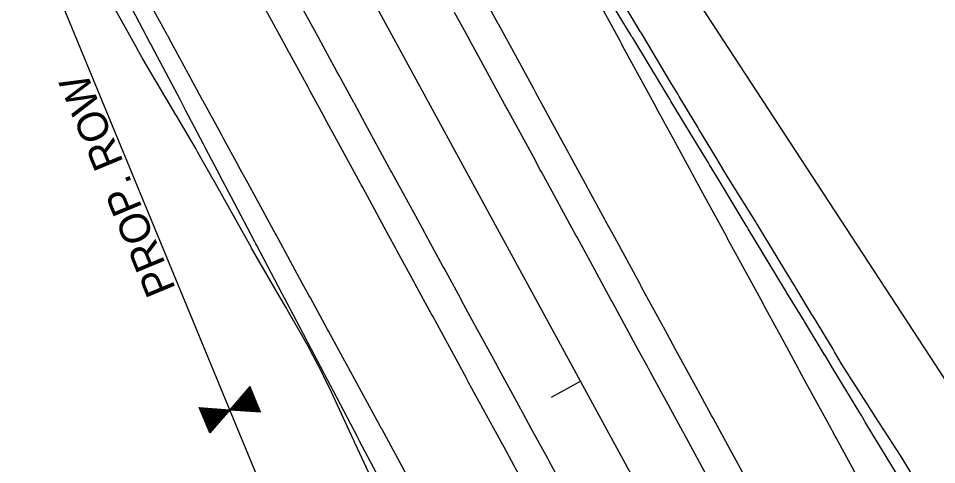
# Model space of a CAD drawing. Extents: x 1627557 to 1636561, y 783843 to 794002.
# Drawn here: x 1627879.8 to 1628047.3, y 785040.7 to 785122 of the extents above; entities that cross this region are included whole.
import ezdxf

# ---------------------------------------------------------------- set-up
doc = ezdxf.new("R2010")
doc.units = 0
for name, color, linetype in [('GATE', 7, 'Continuous'), ('R_Clearzone', 7, 'Continuous'), ('R_Ditch', 7, 'Continuous'), ('R_Horz Alg', 7, 'Continuous'), ('R_Horz Alg Annot', 7, 'Continuous'), ('R_Proposed Const Limits', 7, 'Continuous'), ('R_Proposed Road', 7, 'Continuous'), ('R_Proposed Shoulder', 7, 'Continuous'), ('R_ROW', 7, 'Continuous'), ('R_ROW Annot Labels', 7, 'Continuous')]:
    doc.layers.add(name, color=color, linetype=linetype)

msp = doc.modelspace()

# ---------------------------------------------------------------- linework, layer by layer
at = {"layer": 'GATE'}
for p, q in [((1627921.73, 785054.58), (1627923.49, 785050.35)), ((1627921.81, 785054.67), (1627923.6, 785050.34)), ((1627921.88, 785054.75), (1627923.71, 785050.33)), ((1627921.95, 785054.84), (1627923.82, 785050.32)), ((1627922.03, 785054.92), (1627923.93, 785050.31)), ((1627920.27, 785052.9), (1627921.26, 785050.51)), ((1627920.34, 785052.98), (1627921.37, 785050.5)), ((1627920.42, 785053.06), (1627921.48, 785050.49)), ((1627920.49, 785053.15), (1627921.59, 785050.48)), ((1627920.56, 785053.23), (1627921.7, 785050.47)), ((1627920.63, 785053.32), (1627921.82, 785050.47)), ((1627920.71, 785053.4), (1627921.93, 785050.46)), ((1627920.78, 785053.49), (1627922.04, 785050.45)), ((1627920.85, 785053.57), (1627922.15, 785050.44)), ((1627920.93, 785053.66), (1627922.26, 785050.43)), ((1627921, 785053.74), (1627922.37, 785050.43)), ((1627921.07, 785053.82), (1627922.48, 785050.42)), ((1627921.15, 785053.91), (1627922.6, 785050.41)), ((1627921.22, 785053.99), (1627922.71, 785050.4)), ((1627921.29, 785054.08), (1627922.82, 785050.39)), ((1627921.37, 785054.16), (1627922.93, 785050.39)), ((1627921.44, 785054.25), (1627923.04, 785050.38)), ((1627921.51, 785054.33), (1627923.15, 785050.37)), ((1627921.59, 785054.42), (1627923.26, 785050.36)), ((1627921.66, 785054.5), (1627923.38, 785050.35)), ((1627918.88, 785051.29), (1627919.14, 785050.66)), ((1627918.95, 785051.38), (1627919.25, 785050.65)), ((1627919.02, 785051.46), (1627919.36, 785050.64)), ((1627919.1, 785051.54), (1627919.47, 785050.63)), ((1627919.17, 785051.63), (1627919.58, 785050.63)), ((1627919.24, 785051.71), (1627919.7, 785050.62)), ((1627919.32, 785051.8), (1627919.81, 785050.61)), ((1627919.39, 785051.88), (1627919.92, 785050.6)), ((1627919.46, 785051.97), (1627920.03, 785050.59)), ((1627919.54, 785052.05), (1627920.14, 785050.59)), ((1627919.61, 785052.14), (1627920.25, 785050.58)), ((1627919.68, 785052.22), (1627920.37, 785050.57)), ((1627919.76, 785052.3), (1627920.48, 785050.56)), ((1627919.83, 785052.39), (1627920.59, 785050.55)), ((1627919.9, 785052.47), (1627920.7, 785050.55)), ((1627919.98, 785052.56), (1627920.81, 785050.54)), ((1627920.05, 785052.64), (1627920.92, 785050.53)), ((1627920.12, 785052.73), (1627921.03, 785050.52)), ((1627920.2, 785052.81), (1627921.15, 785050.51)), ((1627912.88, 785051.1), (1627914.76, 785046.55)), ((1627912.99, 785051.1), (1627914.84, 785046.63)), ((1627913.1, 785051.09), (1627914.91, 785046.72)), ((1627913.21, 785051.08), (1627914.98, 785046.8)), ((1627913.32, 785051.07), (1627915.06, 785046.89)), ((1627913.44, 785051.06), (1627915.13, 785046.97)), ((1627913.55, 785051.06), (1627915.2, 785047.06)), ((1627913.66, 785051.05), (1627915.28, 785047.14)), ((1627913.77, 785051.04), (1627915.35, 785047.22)), ((1627913.88, 785051.03), (1627915.42, 785047.31)), ((1627913.99, 785051.02), (1627915.5, 785047.39)), ((1627914.1, 785051.02), (1627915.57, 785047.48)), ((1627914.22, 785051.01), (1627915.64, 785047.56)), ((1627914.33, 785051), (1627915.71, 785047.65)), ((1627914.44, 785050.99), (1627915.79, 785047.73)), ((1627914.55, 785050.98), (1627915.86, 785047.82)), ((1627914.66, 785050.98), (1627915.93, 785047.9)), ((1627914.77, 785050.97), (1627916.01, 785047.98)), ((1627914.88, 785050.96), (1627916.08, 785048.07)), ((1627915, 785050.95), (1627916.15, 785048.15)), ((1627915.11, 785050.94), (1627916.23, 785048.24)), ((1627915.22, 785050.94), (1627916.3, 785048.32)), ((1627915.33, 785050.93), (1627916.37, 785048.41)), ((1627915.44, 785050.92), (1627916.45, 785048.49)), ((1627915.55, 785050.91), (1627916.52, 785048.58)), ((1627915.67, 785050.9), (1627916.59, 785048.66)), ((1627915.78, 785050.9), (1627916.67, 785048.74)), ((1627915.89, 785050.89), (1627916.74, 785048.83)), ((1627916, 785050.88), (1627916.81, 785048.91)), ((1627916.11, 785050.87), (1627916.89, 785049)), ((1627916.22, 785050.86), (1627916.96, 785049.08)), ((1627916.33, 785050.86), (1627917.03, 785049.17)), ((1627916.45, 785050.85), (1627917.11, 785049.25)), ((1627916.56, 785050.84), (1627917.18, 785049.34)), ((1627916.67, 785050.83), (1627917.25, 785049.42)), ((1627916.78, 785050.82), (1627917.33, 785049.5)), ((1627916.89, 785050.82), (1627917.4, 785049.59)), ((1627917, 785050.81), (1627917.47, 785049.67)), ((1627917.12, 785050.8), (1627917.55, 785049.76)), ((1627917.23, 785050.79), (1627917.62, 785049.84)), ((1627917.34, 785050.79), (1627917.69, 785049.93)), ((1627917.45, 785050.78), (1627917.77, 785050.01)), ((1627917.56, 785050.77), (1627917.84, 785050.1)), ((1627917.67, 785050.76), (1627917.91, 785050.18)), ((1627917.78, 785050.75), (1627917.99, 785050.26)), ((1627917.9, 785050.75), (1627918.06, 785050.35)), ((1627918.01, 785050.74), (1627918.13, 785050.43)), ((1627918.12, 785050.73), (1627918.21, 785050.52)), ((1627918.23, 785050.72), (1627918.28, 785050.6)), ((1627918.34, 785050.71), (1627918.35, 785050.69)), ((1627918.44, 785050.78), (1627918.47, 785050.7)), ((1627918.51, 785050.87), (1627918.58, 785050.7)), ((1627918.58, 785050.95), (1627918.69, 785050.69)), ((1627918.66, 785051.04), (1627918.8, 785050.68)), ((1627918.73, 785051.12), (1627918.92, 785050.67)), ((1627918.8, 785051.21), (1627919.03, 785050.66))]:
    msp.add_line(p, q, dxfattribs=at)
for points in [[(1627922.04, 785054.93), (1627918.37, 785050.71), (1627923.95, 785050.31)], [(1627912.8, 785051.11), (1627918.37, 785050.71), (1627914.71, 785046.49)]]:
    msp.add_lwpolyline(points, close=True, dxfattribs=at)
at = {"layer": 'R_Clearzone'}
for points in [[(1627950.73, 785038.65), (1627946.07, 785047.2), (1627945.94, 785047.43), (1627945.85, 785047.61), (1627945.73, 785047.82), (1627941.16, 785056.21), (1627939.56, 785059.13), (1627939.35, 785059.52), (1627936.37, 785064.99), (1627936.18, 785065.33), (1627933.06, 785071.07), (1627932.86, 785071.43), (1627931.58, 785073.77), (1627926.8, 785082.55), (1627926.63, 785082.84), (1627926.51, 785083.08), (1627926.39, 785083.29), (1627922.01, 785091.33), (1627919.96, 785095.09), (1627919.93, 785095.14), (1627917.22, 785100.11), (1627916.84, 785100.81), (1627913.46, 785107), (1627913.41, 785107.1), (1627912.43, 785108.89), (1627907.65, 785117.67), (1627907.04, 785118.78), (1627907, 785118.85), (1627906.86, 785119.11), (1627902.86, 785126.45)], [(1628033.09, 785038), (1628028.96, 785045.57), (1628028.78, 785045.9), (1628028.31, 785046.78), (1628028.04, 785047.26), (1628023.52, 785055.56), (1628022.3, 785057.79), (1628022.05, 785058.25), (1628018.73, 785064.34), (1628018.49, 785064.77), (1628015.79, 785069.73), (1628015.56, 785070.16), (1628013.95, 785073.12), (1628009.28, 785081.66), (1628009.16, 785081.89), (1628009.06, 785082.07), (1628008.95, 785082.29), (1628004.37, 785090.67), (1628002.78, 785093.6), (1628002.57, 785093.98), (1627999.58, 785099.45), (1627999.4, 785099.8), (1627996.27, 785105.53), (1627996.07, 785105.9), (1627994.8, 785108.23), (1627990.01, 785117.01), (1627989.85, 785117.31), (1627989.72, 785117.54), (1627989.61, 785117.75), (1627985.22, 785125.79)]]:
    msp.add_lwpolyline(points, dxfattribs=at)
at = {"layer": 'R_Ditch'}
for points in [[(1628041.37, 785036.75), (1628038.75, 785041.08), (1628034.27, 785048.46), (1628034.07, 785048.79), (1628033.56, 785049.64), (1628033.27, 785050.11), (1628028.37, 785058.2), (1628027.05, 785060.38), (1628026.77, 785060.83), (1628023.18, 785066.76), (1628022.92, 785067.18), (1628019.99, 785072.02), (1628019.73, 785072.44), (1628017.99, 785075.32), (1628012.93, 785083.65), (1628012.8, 785083.88), (1628012.69, 785084.05), (1628012.57, 785084.26), (1628007.61, 785092.44), (1628005.88, 785095.29), (1628005.65, 785095.67), (1628002.42, 785101), (1628002.21, 785101.33), (1627998.82, 785106.92), (1627998.61, 785107.28), (1627997.23, 785109.56), (1627992.04, 785118.12), (1627991.86, 785118.41), (1627991.72, 785118.64), (1627991.6, 785118.84), (1627986.85, 785126.68)], [(1627946.58, 785036.39), (1627942.05, 785045), (1627941.92, 785045.24), (1627941.83, 785045.42), (1627941.72, 785045.63), (1627937.26, 785054.08), (1627935.71, 785057.03), (1627935.51, 785057.42), (1627932.6, 785062.93), (1627932.42, 785063.28), (1627929.38, 785069.06), (1627929.18, 785069.43), (1627927.94, 785071.78), (1627923.28, 785080.63), (1627923.12, 785080.93), (1627923, 785081.16), (1627922.89, 785081.38), (1627918.62, 785089.48), (1627916.62, 785093.27), (1627916.6, 785093.32), (1627913.96, 785098.33), (1627913.59, 785099.04), (1627910.3, 785105.27), (1627910.25, 785105.38), (1627909.3, 785107.18), (1627904.64, 785116.03), (1627904.05, 785117.15), (1627904.01, 785117.22), (1627903.87, 785117.48), (1627899.98, 785124.87)]]:
    msp.add_lwpolyline(points, dxfattribs=at)
at = {"layer": 'R_Horz Alg'}
msp.add_line((1628236.53, 784589.68), (1627810.31, 785371.39), dxfattribs=at)
at = {"layer": 'R_Horz Alg Annot'}
msp.add_lwpolyline([(1627977.07, 785053.01), (1627982.34, 785055.88)], dxfattribs=at)
at = {"layer": 'R_Proposed Const Limits'}
for points in [[(1628043.44, 785037.88), (1628040.79, 785042.19), (1628036.1, 785049.46), (1628035.89, 785049.78), (1628035.36, 785050.62), (1628035.06, 785051.08), (1628029.93, 785059.05), (1628028.67, 785061.26), (1628028.41, 785061.72), (1628024.81, 785067.65), (1628024.55, 785068.07), (1628021.61, 785072.9), (1628021.35, 785073.32), (1628019.6, 785076.2), (1628014.53, 785084.52), (1628014.39, 785084.75), (1628014.29, 785084.92), (1628014.16, 785085.13), (1628009.11, 785093.26), (1628007.39, 785096.11), (1628007.16, 785096.49), (1628003.94, 785101.83), (1628003.73, 785102.16), (1628000.35, 785107.75), (1628000.13, 785108.11), (1627998.75, 785110.39), (1627993.61, 785118.98), (1627993.44, 785119.27), (1627993.3, 785119.5), (1627993.18, 785119.7), (1627988.48, 785127.57)], [(1627945.35, 785035.71), (1627941.23, 785044.56), (1627941.12, 785044.8), (1627941.03, 785044.98), (1627940.93, 785045.2), (1627936.89, 785053.88), (1627935.46, 785056.89), (1627935.25, 785057.28), (1627932.36, 785062.8), (1627932.18, 785063.15), (1627928.92, 785068.81), (1627928.71, 785069.17), (1627927.37, 785071.47), (1627922.35, 785080.12), (1627922.18, 785080.42), (1627922.05, 785080.65), (1627921.93, 785080.85), (1627917.46, 785088.84), (1627915.39, 785092.6), (1627915.36, 785092.65), (1627912.56, 785097.56), (1627912.15, 785098.26), (1627908.57, 785104.33), (1627908.51, 785104.43), (1627907.48, 785106.18), (1627902.4, 785114.8), (1627901.76, 785115.9), (1627901.71, 785115.97), (1627901.57, 785116.23), (1627897.53, 785123.54)]]:
    msp.add_lwpolyline(points, dxfattribs=at)
at = {"layer": 'R_Proposed Road'}
for points in [[(1627979.91, 785035.27), (1627976.59, 785041.36), (1627976.35, 785041.79), (1627973.65, 785046.75), (1627973.41, 785047.18), (1627971.8, 785050.14), (1627967.14, 785058.68), (1627967.02, 785058.92), (1627966.92, 785059.1), (1627966.8, 785059.31), (1627962.23, 785067.7), (1627960.63, 785070.62), (1627960.42, 785071.01), (1627957.44, 785076.48), (1627957.25, 785076.82), (1627954.13, 785082.55), (1627953.93, 785082.92), (1627952.65, 785085.26), (1627947.87, 785094.04), (1627947.7, 785094.33), (1627947.58, 785094.57), (1627947.46, 785094.77), (1627943.08, 785102.82), (1627941.03, 785106.58), (1627941, 785106.63), (1627938.29, 785111.6), (1627937.91, 785112.3), (1627934.54, 785118.49), (1627934.48, 785118.59), (1627933.51, 785120.38), (1627928.72, 785129.15)], [(1628006.97, 785035.77), (1628002.45, 785044.07), (1628001.23, 785046.3), (1628000.98, 785046.76), (1627997.66, 785052.85), (1627997.42, 785053.28), (1627994.72, 785058.24), (1627994.48, 785058.67), (1627992.87, 785061.63), (1627988.21, 785070.17), (1627988.09, 785070.41), (1627987.99, 785070.58), (1627987.87, 785070.8), (1627983.3, 785079.19), (1627981.71, 785082.11), (1627981.49, 785082.5), (1627978.51, 785087.97), (1627978.33, 785088.31), (1627975.2, 785094.04), (1627975, 785094.41), (1627973.73, 785096.75), (1627968.94, 785105.52), (1627968.78, 785105.82), (1627968.65, 785106.05), (1627968.54, 785106.26), (1627964.15, 785114.3), (1627962.1, 785118.07), (1627962.07, 785118.12), (1627959.36, 785123.08)]]:
    msp.add_lwpolyline(points, dxfattribs=at)
at = {"layer": 'R_Proposed Shoulder'}
for points in [[(1627971.08, 785038.92), (1627968.38, 785043.88), (1627968.15, 785044.31), (1627966.53, 785047.27), (1627961.87, 785055.81), (1627961.75, 785056.04), (1627961.65, 785056.22), (1627961.53, 785056.44), (1627956.96, 785064.82), (1627955.37, 785067.75), (1627955.16, 785068.13), (1627952.17, 785073.6), (1627951.99, 785073.95), (1627948.86, 785079.68), (1627948.66, 785080.05), (1627947.39, 785082.38), (1627942.6, 785091.16), (1627942.44, 785091.46), (1627942.31, 785091.69), (1627942.2, 785091.9), (1627937.81, 785099.94), (1627935.76, 785103.71), (1627935.73, 785103.76), (1627933.03, 785108.72), (1627932.64, 785109.43), (1627929.27, 785115.62), (1627929.21, 785115.72), (1627928.24, 785117.5), (1627923.45, 785126.28)], [(1628012.24, 785038.64), (1628007.72, 785046.94), (1628006.5, 785049.18), (1628006.25, 785049.63), (1628002.93, 785055.72), (1628002.69, 785056.16), (1627999.99, 785061.11), (1627999.75, 785061.54), (1627998.14, 785064.5), (1627993.48, 785073.05), (1627993.35, 785073.28), (1627993.26, 785073.46), (1627993.14, 785073.67), (1627988.57, 785082.06), (1627986.97, 785084.98), (1627986.76, 785085.37), (1627983.78, 785090.84), (1627983.59, 785091.18), (1627980.47, 785096.92), (1627980.27, 785097.28), (1627978.99, 785099.62), (1627974.21, 785108.4), (1627974.04, 785108.69), (1627973.92, 785108.93), (1627973.8, 785109.14), (1627969.42, 785117.18), (1627967.37, 785120.94), (1627967.34, 785120.99), (1627964.63, 785125.96)]]:
    msp.add_lwpolyline(points, dxfattribs=at)
at = {"layer": 'R_ROW'}
for p, q in [((1628058.95, 785040.71), (1627921.72, 785250.62)), ((1627959.18, 784952.13), (1627851.48, 785212.33))]:
    msp.add_line(p, q, dxfattribs=at)

# ---------------------------------------------------------------- texts
at = {"layer": 'R_ROW Annot Labels'}
msp.add_text('PROP. ROW', height=5.5, rotation=112.4833, dxfattribs=at).set_placement((1627908.57, 785072.74))

doc.saveas('drawing.dxf')
